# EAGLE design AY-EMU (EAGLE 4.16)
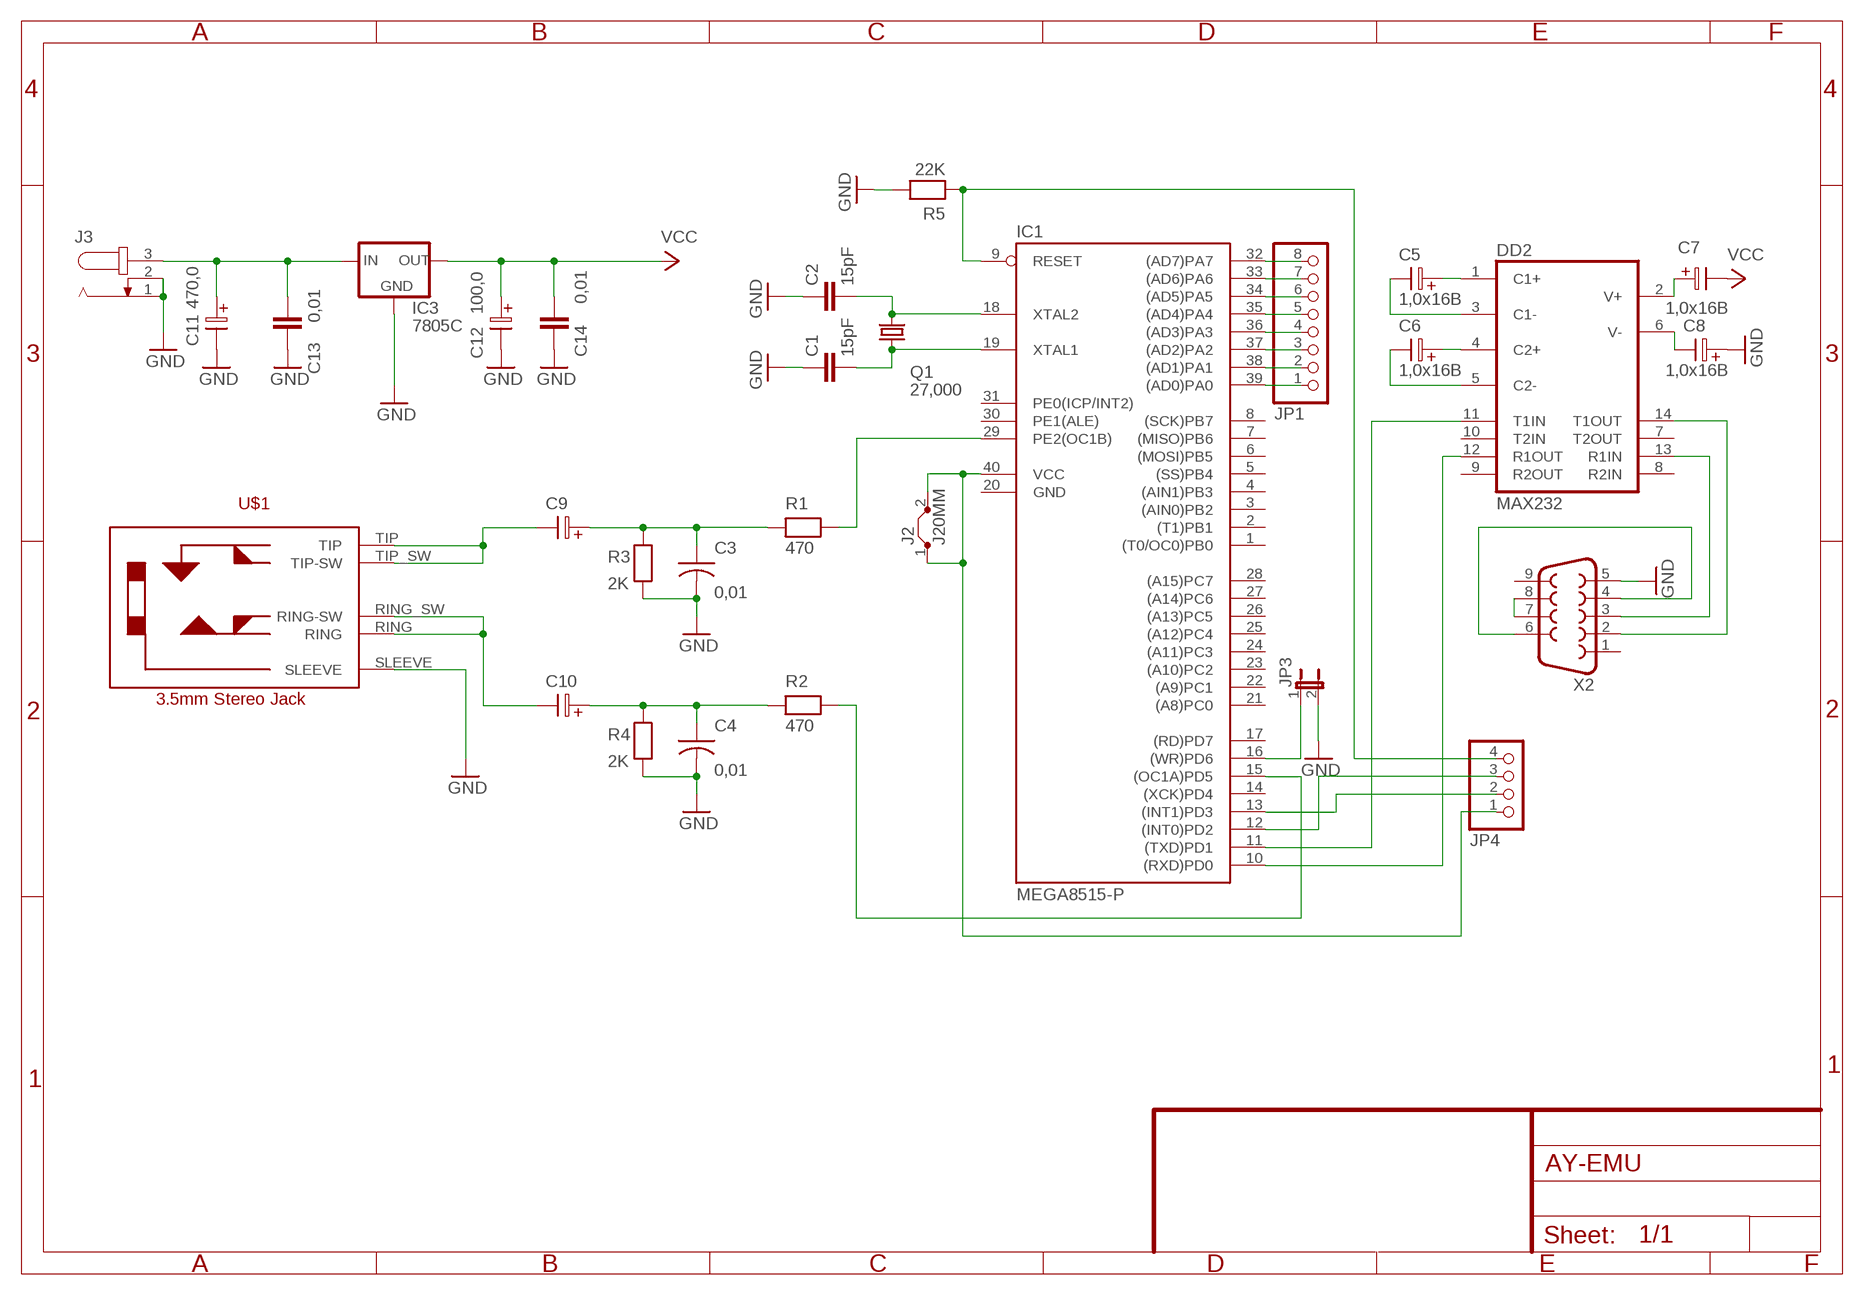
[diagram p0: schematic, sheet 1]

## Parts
C1  15pF  C-EU025-024X044  [C025-024X044]
C2  15pF  C-EU025-024X044  [C025-024X044]
C3  0,01  CAP-5  [C-5]
C4  0,01  CAP-5  [C-5]
C5  1,0x16B  ELC-2,5L  [ES-2,5L]
C6  1,0x16B  ELC-2,5L  [ES-2,5L]
C7  1,0x16B  ELC-2,5L  [ES-2,5L]
C8  1,0x16B  ELC-2,5L  [ES-2,5L]
C9  ELC-2,5L  [ES-2,5L]
C10  ELC-2,5L  [ES-2,5L]
C11  470,0  ELC-5  [ES-5]
C12  100,0  ELC-2,5L  [ES-2,5L]
C13  0,01  C-EU025-024X044  [C025-024X044]
C14  0,01  C-EU025-024X044  [C025-024X044]
DD2  MAX232  [DIL16]
IC1  MEGA8515-P  [DIL40]
IC3  7805C  78XXS  [78XXS]
J2  J20MM  [20]
J3  JACK-PLUG0  [SPC4077]
JP1  PINHD-1X8  [1X08]
JP3  JP1E  [JP1]
JP4  PINHD-1X4  [1X04]
Q1  27,000  CRYSTALHC49U70  [HC49U70]
R1  470  RESEU-12,5  [R-12,5]
R2  470  RESEU-12,5  [R-12,5]
R3  2K  RESEU-12,5  [R-12,5]
R4  2K  RESEU-12,5  [R-12,5]
R5  22K  RESEU-12,5  [R-12,5]
U$1  PICAXE_STEREOJACKSOCKET  [PICAXE_STEREOJACKSOCKET]
X2  F09H  [F09H]

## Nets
GND: C1.1 C2.1 C3.2 C4.2 C8.1 C11.2 C12.2 C13.1 C14.1 IC3.GND J3.1 J3.2 JP3.2 R3.1 R4.1 R5.2 U$1.SLEEVE X2.5
N$1: C2.2 IC1.18(XTAL2) Q1.2
N$2: C1.2 IC1.19(XTAL1) Q1.1
N$3: C5.1 DD2.1(C1+)
N$4: C5.2 DD2.3(C1-)
N$5: C6.1 DD2.4(C2+)
N$6: C6.2 DD2.5(C2-)
N$7: C7.1 DD2.2(V+)
N$8: C8.2 DD2.6(V-)
N$9: X2.4 X2.6
N$10: X2.7 X2.8
N$11: DD2.14(T1OUT) X2.2
N$12: DD2.13(R1IN) X2.3
N$13: DD2.12(R1OUT) IC1.10((RXD)PD0)
N$14: DD2.11(T1IN) IC1.11((TXD)PD1)
N$15: IC1.29(PE2(OC1B)) R1.2
N$16: IC1.15((OC1A)PD5) R2.2
N$17: C9.2 U$1.TIP U$1.TIP_SW(TIP-SW)
N$18: C3.1 C9.1 R1.1 R3.2
N$19: C4.1 C10.1 R2.1 R4.2
N$20: C10.2 U$1.RING U$1.RING_SW(RING-SW)
N$21: IC1.9(RESET) JP4.4 R5.1
N$22: IC1.32((AD7)PA7) JP1.8
N$23: IC1.33((AD6)PA6) JP1.7
N$24: IC1.34((AD5)PA5) JP1.6
N$25: IC1.35((AD4)PA4) JP1.5
N$26: IC1.36((AD3)PA3) JP1.4
N$27: IC1.37((AD2)PA2) JP1.3
N$28: IC1.38((AD1)PA1) JP1.2
N$29: IC1.39((AD0)PA0) JP1.1
N$30: IC1.12((INT0)PD2) JP4.3
N$31: IC1.13((INT1)PD3) JP4.2
N$32: C11.1 C13.2 IC3.IN J3.3
N$33: IC1.40(VCC) J2.1 J2.2 JP4.1
N$34: IC1.16((WR)PD6) JP3.1
VCC: C7.2 C12.1 C14.2 IC3.OUT
Unconnected: DD2.7(T2OUT) DD2.8(R2IN) DD2.9(R2OUT) DD2.10(T2IN) IC1.1((T0/OC0)PB0) IC1.2((T1)PB1) IC1.3((AIN0)PB2) IC1.4((AIN1)PB3) IC1.5((SS)PB4) IC1.6((MOSI)PB5) IC1.7((MISO)PB6) IC1.8((SCK)PB7) IC1.14((XCK)PD4) IC1.17((RD)PD7) IC1.21((A8)PC0) IC1.22((A9)PC1) IC1.23((A10)PC2) IC1.24((A11)PC3) IC1.25((A12)PC4) IC1.26((A13)PC5) IC1.27((A14)PC6) IC1.28((A15)PC7) IC1.30(PE1(ALE)) IC1.31(PE0(ICP/INT2)) X2.1 X2.9

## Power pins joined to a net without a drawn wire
GND: DD2.15(GND) IC1.20(GND)
VCC: DD2.16(VCC)

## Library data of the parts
C1 C2 C13 C14 = rcl:C-EU: CAPACITOR, European symbol
C3 C4 = discrete:CAP-5
C5-C10 C12 = discrete:ELC-2,5L
C11 = discrete:ELC-5
DD2 = maxim:MAX232: RS232 TRANSEIVER
IC1 = Atmel:MEGA8515-P: MICROCONTROLLER 8 Kbytes FLASH 512 bytes SRAM 512 bytes EEPROM USART 8-channel 10 bit ADC Source: avr.lbr
IC3 = v-reg:78XXS: VOLTAGE REGULATOR
J2 = Jumper:J: Bridge
J3 = Con-jack:JACK-PLUG: DC POWER JACK Power Jack, DC, Right Angle, Through Hole, Rated 5A at 16VDC, PC Terminals Distributor: Farnell (www.Farnell.de) Drawing: 84N1161.pdf / 84N1162.pdf Manufacturer: SPC Technology (www.spctechnology.com) Type: SPC4077 / SPC 4078
JP1 = Pinhead:PINHD-1X8: PIN HEADER
JP3 = Jumper:JP1E: JUMPER
JP4 = Pinhead:PINHD-1X4: PIN HEADER
Q1 = crystal:CRYSTAL: CRYSTAL
R1-R5 = discrete:RESEU-12,5
U$1 = PICAXE_StereoJackSocket:PICAXE_STEREOJACKSOCKET
X2 = con-subd:F09: SUB-D

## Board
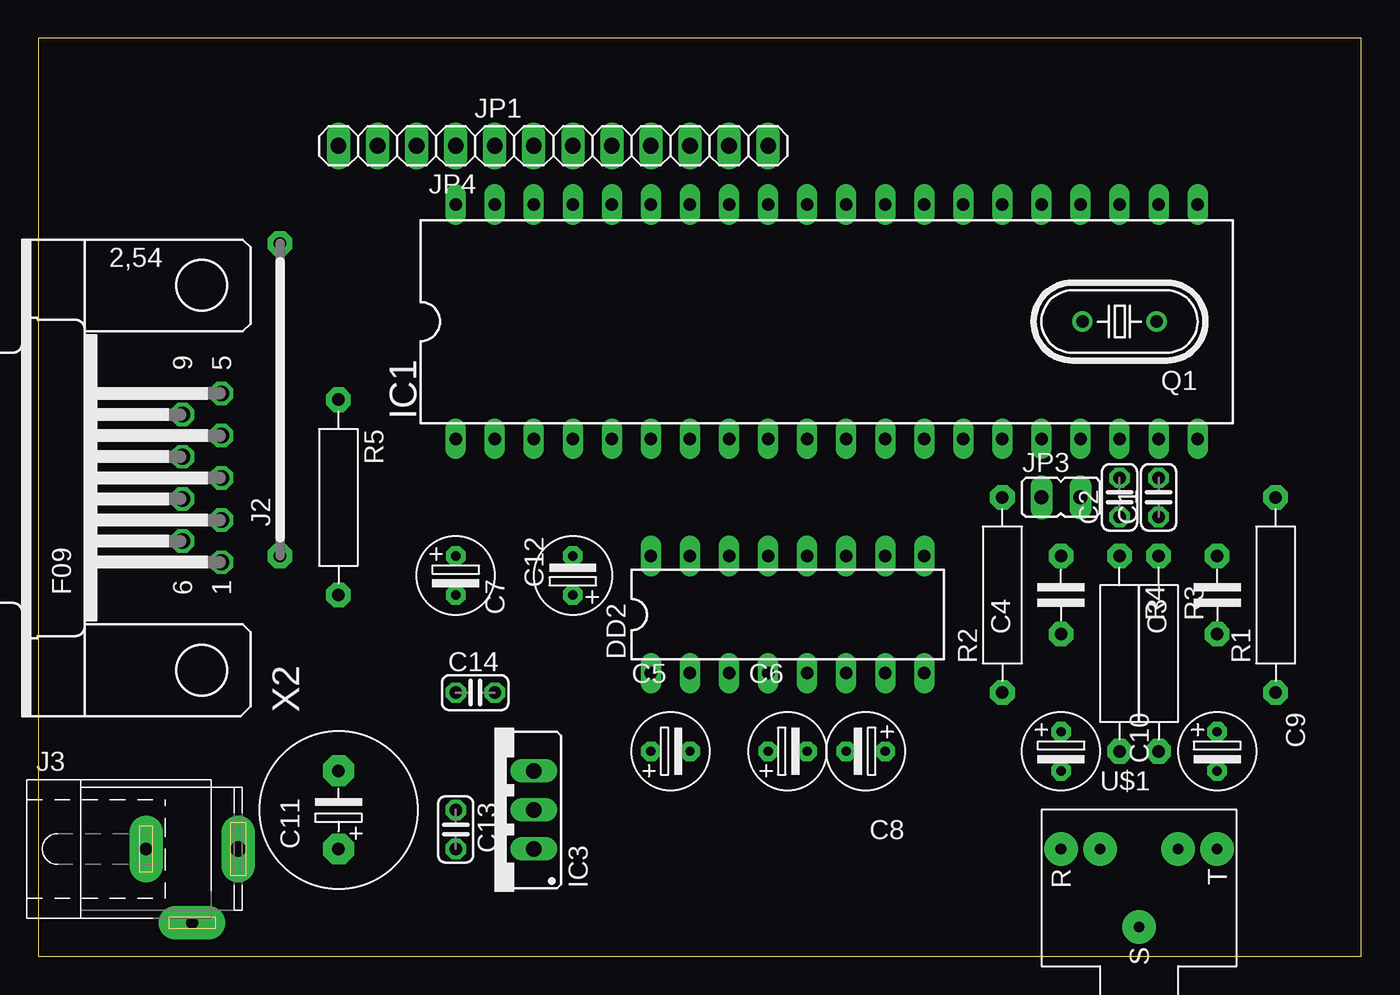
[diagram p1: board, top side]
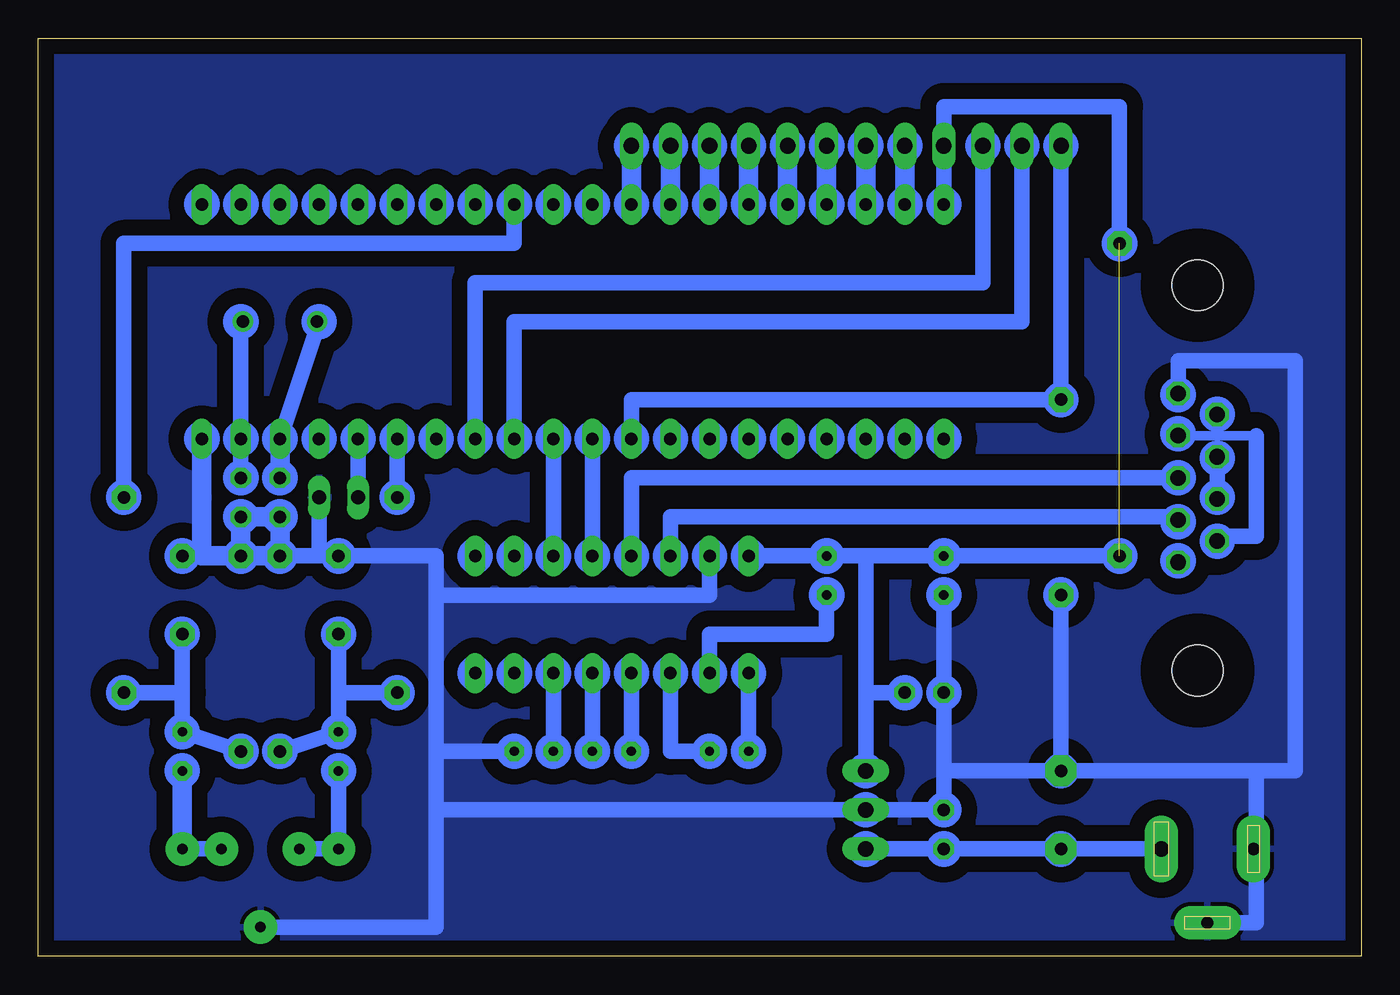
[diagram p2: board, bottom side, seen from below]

Size 86.03 x 59.67 mm. Coordinates in mm from the lower left corner, seen from the top.
Outline: 0,59.67 0,0 86.03,0 86.03,59.67 0,59.67
Copper layers (1*16): Top 0.035mm / dielectric 1.5mm / Bottom 0.035mm
Design rules "default": minimum track width 10mil, minimum drill 24mil, track to track 8mil, track to pad 8mil, pad to pad 8mil, via to via 8mil, smd to smd 8mil, copper to edge 40mil, drill to drill 8mil, minimum pad ring 10mil, minimum via ring 8mil, stop-mask expansion 4mil, vias tented up to drill 0mil, thermal gap 10mil

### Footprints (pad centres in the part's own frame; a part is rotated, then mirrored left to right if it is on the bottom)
C025-024X044 = drill 0.813 octagon: 1 -1.27,0; 2 1.27,0
C-5 = drill 0.813 pad 1.6 octagon: 1 -2.54,0; 2 2.54,0
ES-2,5L = drill 0.61 pad 1.27 octagon: 1 0,0; 2 2.54,0
ES-5 = drill 0.813 pad 2.007 octagon: 1 -2.54,0; 2 2.54,0
DIL16 = drill 0.813 long: 1 -8.89,-3.81; 2 -6.35,-3.81; 3 -3.81,-3.81; 4 -1.27,-3.81; 5 1.27,-3.81; 6 3.81,-3.81; 7 6.35,-3.81; 8 8.89,-3.81; 9 8.89,3.81; 10 6.35,3.81; 11 3.81,3.81; 12 1.27,3.81; 13 -1.27,3.81; 14 -3.81,3.81; 15 -6.35,3.81; 16 -8.89,3.81
DIL40 = drill 0.813 long: 1 -24.13,-7.62; 2 -21.59,-7.62; 3 -19.05,-7.62; 4 -16.51,-7.62; 5 -13.97,-7.62; 6 -11.43,-7.62; 7 -8.89,-7.62; 8 -6.35,-7.62; 9 -3.81,-7.62; 10 -1.27,-7.62; 11 1.27,-7.62; 12 3.81,-7.62; 13 6.35,-7.62; 14 8.89,-7.62; 15 11.43,-7.62; 16 13.97,-7.62; 17 16.51,-7.62; 18 19.05,-7.62; 19 21.59,-7.62; 20 24.13,-7.62; 21 24.13,7.62; 22 21.59,7.62; 23 19.05,7.62; 24 16.51,7.62; 25 13.97,7.62; 26 11.43,7.62; 27 8.89,7.62; 28 6.35,7.62; 29 3.81,7.62; 30 1.27,7.62; 31 -1.27,7.62; 32 -3.81,7.62; 33 -6.35,7.62; 34 -8.89,7.62; 35 -11.43,7.62; 36 -13.97,7.62; 37 -16.51,7.62; 38 -19.05,7.62; 39 -21.59,7.62; 40 -24.13,7.62
78XXS = drill 1.016 long: GND 0,-2.54; IN -2.54,-2.54; OUT 2.54,-2.54
20 = drill 0.813 pad 1.6 octagon: 1 -10.16,0; 2 10.16,0
SPC4077 = drill 0.8 pad 2.184 long: 1 -3,0; 2 0,-4.8 | drill 1 pad 2.184 long: 3 3,0
1X08 = drill 1.016 long: 1 -8.89,0; 2 -6.35,0; 3 -3.81,0; 4 -1.27,0; 5 1.27,0; 6 3.81,0; 7 6.35,0; 8 8.89,0
JP1 = drill 0.914 long: 1 0,-1.27; 2 0,1.27
1X04 = drill 1.016 long: 1 -3.81,0; 2 -1.27,0; 3 1.27,0; 4 3.81,0
HC49U70 = drill 0.813 round: 1 -2.413,0; 2 2.413,0
R-12,5 = drill 0.813 pad 1.6 octagon: 1 -6.35,0; 2 6.35,0
PICAXE_STEREOJACKSOCKET = drill 0.7 pad 2.184 round: RING -5.08,-5.08; RING_SW -5.08,-2.54; SLEEVE 0,0; TIP -5.08,5.08; TIP_SW -5.08,2.54
F09H = drill 1.016 octagon: 1 -5.486,-1.27; 2 -2.743,-1.27; 3 0,-1.27; 4 2.743,-1.27; 5 5.486,-1.27; 6 -4.115,1.27; 7 -1.372,1.27; 8 1.372,1.27; 9 4.115,1.27 | hole 3.302: -12.522,0; 12.522,0

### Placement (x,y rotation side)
C1  72.86,29.83 90 top
C2  70.32,29.83 90 top
C3  76.67,23.48 90 top
C4  66.51,23.48 90 top
C5  39.84,13.32 0 top
C6  47.46,13.32 0 top
C7  34.76,23.48 90 top
C8  55.08,13.32 180 top
C9  76.67,14.59 270 top
C10  66.51,14.59 270 top
C11  19.52,9.51 90 top
C12  27.14,26.02 270 top
C13  27.14,8.24 270 top
C14  28.41,17.13 0 top
DD2  48.73,22.21 0 top
IC1  51.27,41.26 0 top
IC3  29.68,9.51 90 top
J2  15.71,36.18 90 top
J3  10,6.97 0 top
JP1  38.57,52.69 0 top
JP3  66.51,29.83 270 top
JP4  23.33,52.69 180 top
Q1  70.32,41.26 180 top
R1  80.48,23.48 90 top
R2  62.7,23.48 90 top
R3  72.86,19.67 270 top
R4  70.32,19.67 270 top
R5  19.52,29.83 270 top
U$1  71.59,1.89 270 top
X2  10.63,31.1 90 top

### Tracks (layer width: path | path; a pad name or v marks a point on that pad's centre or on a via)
GND
  Bottom 1.016: 67.78,26.02 R4.1 | 60.16,13.32 C8.1 | 60.16,23.48 60.16,26.02 67.78,26.02 | 67.78,26.02 C4.2 | R4.1 R3.1 | R4.1 R3.1 | DD2.15 42.38,23.48 60.16,23.48 | 60.16,13.32 60.16,23.48 | 60.16,9.51 60.16,13.32 | C14.1 C12.2 C14.1 | 11.9,36.18 X2.5 11.9,38.72 4.28,38.72 4.28,12.05 | R3.1 C3.2 | U$1.SLEEVE 60.16,1.89 60.16,9.51 | 60.16,9.51 IC3.GND C13.1 C14.1 | C11.2 R5.2 | 6.82,6.97 6.82,12.05 4.28,12.05 | J3.2 6.82,2.17 6.82,6.97 | 6.82,6.97 J3.1 | 67.78,26.02 JP3.2 | 4.28,12.05 C11.2 | C11.2 27.14,12.05 C14.1
  Bottom 1.27: C2.1 C1.1 | R3.1 C1.1 | C2.1 C1.1 | C2.1 R4.1 75.4,26.02 IC1.20
  pour Bottom (isolate 1.016): 0.47,59.04 85.56,59.04 85.56,0.62 0.47,0.62
N$1
  Bottom 1.016: Q1.2 67.78,41.26 IC1.18
  Bottom 1.27: C2.2 IC1.18
N$2
  Bottom 1.016: C1.2 IC1.19 72.86,41.26 Q1.1
N$3
  Bottom 1.016: C5.1 DD2.1
N$4
  Bottom 1.016: C5.2 44.92,13.32 DD2.3
N$5
  Bottom 1.016: C6.1 DD2.4
N$6
  Bottom 1.016: C6.2 DD2.5
N$7
  Bottom 1.016: DD2.2 42.38,20.94 34.76,20.94 C7.1
N$8
  Bottom 1.016: C8.2 DD2.6
N$9
  Bottom 0.61: 6.82,33.84 X2.4 | X2.6 9.36,27.29
  Bottom 1.016: 6.82,33.84 6.82,27.29 9.36,27.29
N$10
  Bottom 1.016: X2.7 X2.8
N$11
  Bottom 1.016: DD2.14 44.92,28.56 11.9,28.56 X2.2
N$12
  Bottom 1.016: DD2.13 47.46,31.1 X2.3
N$13
  Bottom 1.016: DD2.12 IC1.10
N$14
  Bottom 1.016: DD2.11 IC1.11
N$15
  Bottom 1.016: IC1.29 55.08,46.34 80.48,46.34 R1.2
N$16
  Bottom 1.016: R2.2 IC1.15
N$17
  Bottom 1.016: U$1.TIP_SW U$1.TIP
  Bottom 1.27: U$1.TIP C9.2
N$18
  Bottom 1.016: R3.2 C9.1 76.67,17.13 | 76.67,17.13 C3.1 | 76.67,17.13 R1.1
N$19
  Bottom 1.016: 66.51,17.13 C10.1 R4.2 | 66.51,17.13 C4.1 | 66.51,17.13 R2.1
N$20
  Bottom 1.016: U$1.RING_SW U$1.RING C10.2
N$21
  Bottom 1.016: IC1.9 47.46,36.18 R5.1 JP4.4
N$22
  Bottom 1.27: IC1.32 JP1.8
N$23
  Bottom 1.27: IC1.33 JP1.7
N$24
  Bottom 1.27: IC1.34 JP1.6
N$25
  Bottom 1.27: IC1.35 JP1.5
N$26
  Bottom 1.27: IC1.36 JP1.4
N$27
  Bottom 1.27: IC1.37 JP1.3
N$28
  Bottom 1.27: IC1.38 JP1.2
N$29
  Bottom 1.27: IC1.39 JP1.1
N$30
  Bottom 1.016: IC1.12 55.08,41.26 22.06,41.26 JP4.3
N$31
  Bottom 1.016: IC1.13 57.62,43.8 24.6,43.8 JP4.2
N$32
  Bottom 1.016: C11.1 J3.3 C11.1 | C11.1 C13.2 IC3.IN
N$33  (1 unrouted)
  Bottom 1.016: J2.2 15.71,55.23 27.14,55.23 JP4.1 | JP4.1 IC1.40 JP4.1 | J2.1 28.41,26.02
N$34
  Bottom 1.016: JP3.1 IC1.16
VCC
  Bottom 1.016: DD2.16 C7.2 32.22,26.02 | 32.22,17.13 32.22,26.02 | 32.22,26.02 C12.1 | 32.22,17.13 C14.2 | IC3.OUT 32.22,17.13
(copper drawn outside any net)
  shapes: Bottom circle x121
